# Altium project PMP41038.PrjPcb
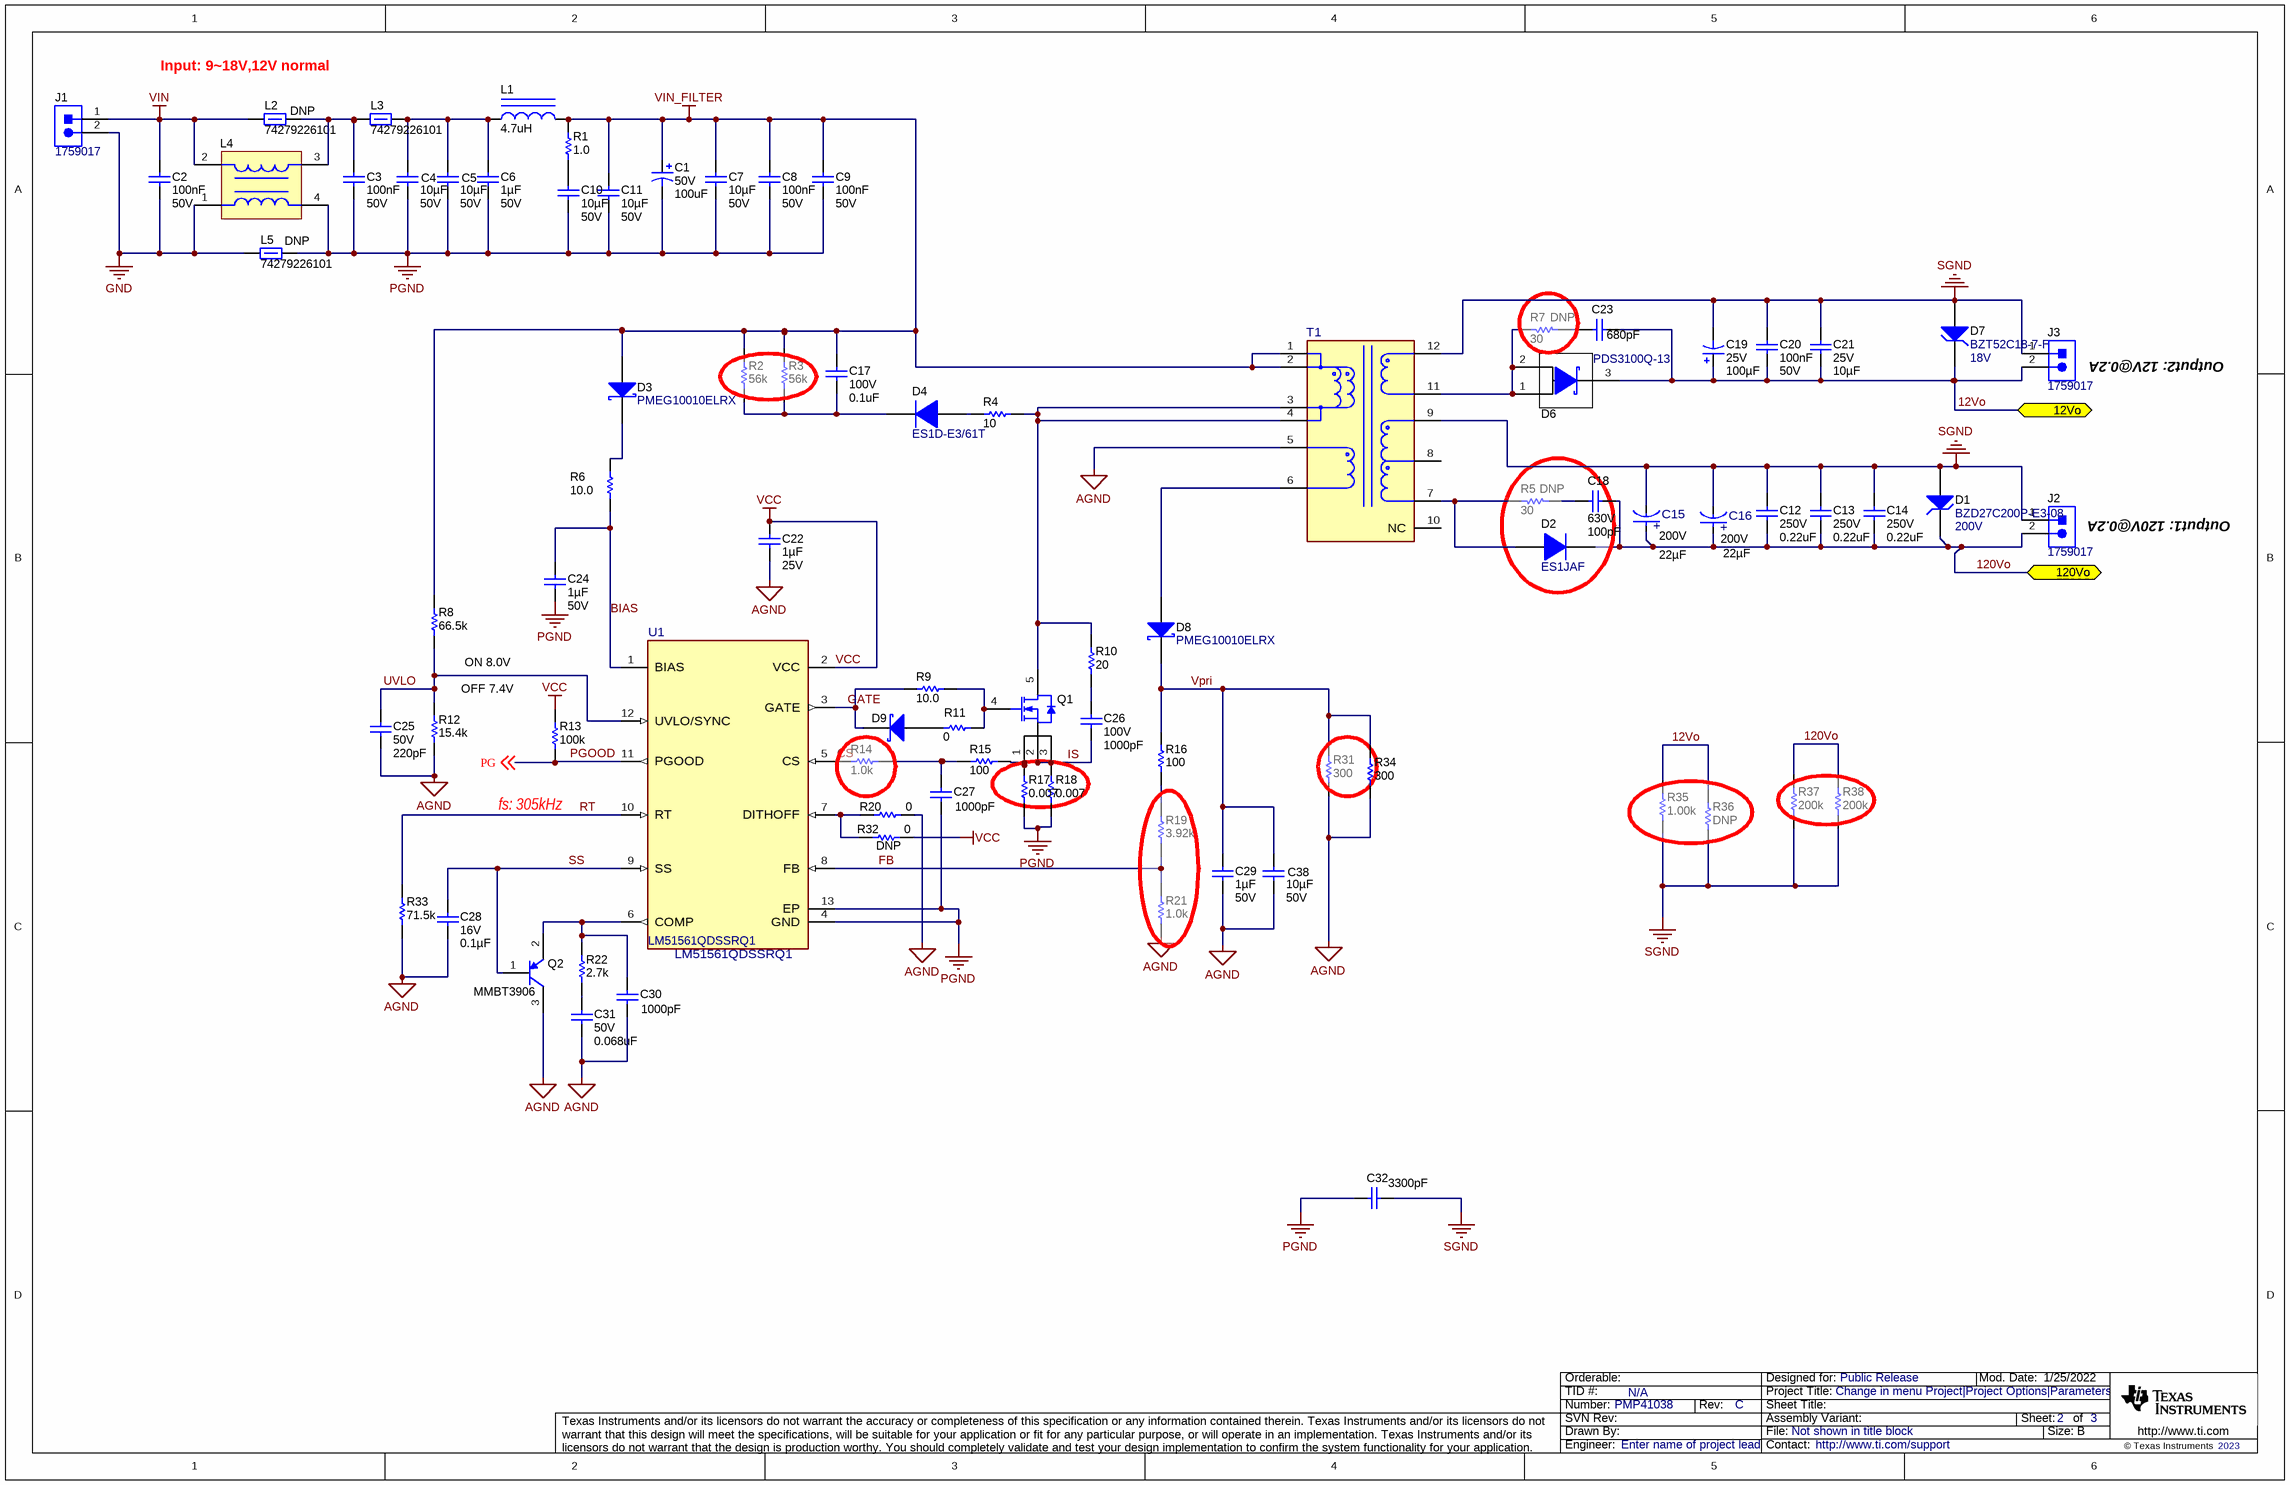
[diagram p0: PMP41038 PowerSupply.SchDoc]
CopyrightYear: 2023; PCB_Layout: Who did the Layout?; PCB_Rev: C; PRJ_Customer: Public Release; PRJ_Engineer: Enter name of project lead; PRJ_Number: PMP41038; PRJ_Title: Change in menu Project|Project Options|Parameters; SCH_Rev: C; TechSupport: http://www.ti.com/support; TID: N/A
3 sheets, 127 parts. Net scope: flat (ports and power ports of the same name join across sheets).
Board file: PMP41038.PcbDoc
Sheets:
  PMP41038 PowerSupply.SchDoc
  PMP41038_Hardware.SchDoc
  PMP41038 Driver.SchDoc

## Sheet PMP41038 PowerSupply.SchDoc
size 431 x 279 mm; Date: Not shown in title block; ApprovedBy: Not shown in title block; CheckedBy: Not shown in title block; Author: Not shown in title block; CompanyName: Not shown in title block; Engineer: Not shown in title block; Organization: Not shown in title block; Address1: Not shown in title block; Address2: Not shown in title block; Address3: Not shown in title block; Address4: Not shown in title block; DocumentNumber: 2; Revision: Use project parameter SCH_Rev; SheetNumber: 2; SheetTotal: 3; PageSetup: Record=PageOptions¦CenterHorizontal=True¦CenterVertical=True¦PrintScale=1.00¦XCorrection=1.00¦YCorrection=1.00¦PrintKind=0¦BorderSize=5000000¦LeftOffset=0¦BottomOffset=0¦Orientation=2¦PaperLength=1000¦PaperWidth=1000¦Scale=100¦PaperSource=15¦PrintQuality=600¦MediaType=1¦DitherType=10¦PaperKind=Letter¦PrintScaleMode=1

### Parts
C1  VDC_V: 50V  ValueDisplayed: 100uF  [SM_RADIAL_10BMM]  (hidden comment: EEHZA1H101P)
C2  Cap_F: 100nF  VDC_V: 50V  [0603]  (hidden comment: CGA3E2X7R1H104K080AA)
C3  Cap_F: 100nF  VDC_V: 50V  [0603]  (hidden comment: CGA3E2X7R1H104K080AA)
C4  ValueDisplayed: 10µF  VDC_V: 50V  [1206_190]  (hidden comment: CGA5L1X7R1H106K160AC)
C5  ValueDisplayed: 10µF  VDC_V: 50V  [1206_190]  (hidden comment: CGA5L1X7R1H106K160AC)
C6  Cap_F: 1µF  VDC_V: 50V  [0805_HV1]  (hidden comment: CGA4J3X7R1H105K125AB)
C7  ValueDisplayed: 10µF  VDC_V: 50V  [1206_190]  (hidden comment: CGA5L1X7R1H106K160AC)
C8  Cap_F: 100nF  VDC_V: 50V  [0603]  (hidden comment: CGA3E2X7R1H104K080AA)
C9  Cap_F: 100nF  VDC_V: 50V  [0603]  (hidden comment: CGA3E2X7R1H104K080AA)
C10  ValueDisplayed: 10µF  VDC_V: 50V  [1206_190]  (hidden comment: CGA5L1X7R1H106K160AC)
C11  ValueDisplayed: 10µF  VDC_V: 50V  [1206_190]  (hidden comment: CGA5L1X7R1H106K160AC)
C12  VDC_V: 250V  ValueDisplayed: 0.22uF  [1210_220]  (hidden comment: GRM32DR72E224KW01L)
C13  VDC_V: 250V  ValueDisplayed: 0.22uF  [1210_220]  (hidden comment: GRM32DR72E224KW01L)
C14  VDC_V: 250V  ValueDisplayed: 0.22uF  [1210_220]  (hidden comment: GRM32DR72E224KW01L)
C15  value 22µF  VDC_V: 200V  [FP-UVK2D220MPD_RADIAL-MFG]  (hidden comment: UVK2D220MPD)
C16  value 22µF  VDC_V: 200V  [FP-UVK2D220MPD_RADIAL-MFG]  (hidden comment: UVK2D220MPD)
C17  VDC_V: 100V  ValueDisplayed: 0.1uF  [1206_180]  (hidden comment: CGA5L2X7R2A104K160AA)
C18  VDC_V: 630V  ValueDisplayed: 100pF  [1206]  (hidden comment: GRM31A5C2J101JW01D)
C19  VDC_V: 25V  ValueDisplayed: 100µF  [Panasonic_D8]  (hidden comment: EEH-ZA1E101XP)
C20  Cap_F: 100nF  VDC_V: 50V  [0603]  (hidden comment: CGA3E2X7R1H104K080AA)
C21  VDC_V: 25V  ValueDisplayed: 10µF  [1206_190]  (hidden comment: CGA5L1X7R1E106K160AE)
C22  Cap_F: 1µF  VDC_V: 25V  [0603]  (hidden comment: GCM188R71E105KA64D)
C23  ValueDisplayed: 680pF  [0603]  (hidden comment: GRM1885C2A681JA01D)
C24  Cap_F: 1µF  VDC_V: 50V  [0805_HV]  (hidden comment: CGA4J3X7R1H105K125AB)
C25  VDC_V: 50V  ValueDisplayed: 220pF  [0402]  (hidden comment: CGA2B2X7R1H221K050BA)
C26  VDC_V: 100V  ValueDisplayed: 1000pF  [0603]  (hidden comment: GCM1885C2A102JA16D)
C27  ValueDisplayed: 1000pF  [0402]  (hidden comment: GCM155R71H102KA37D)
C28  VDC_V: 16V  ValueDisplayed: 0.1µF  [0402]  (hidden comment: GCM155R71C104JA55D)
C29  Cap_F: 1µF  VDC_V: 50V  [0805_HV1]  (hidden comment: CGA4J3X7R1H105K125AB)
C30  ValueDisplayed: 1000pF  [0402]  (hidden comment: GCM155R71H102KA37D)
C31  VDC_V: 50V  ValueDisplayed: 0.068uF  [0402]  (hidden comment: CGA2B3X7R1H683K050BB)
C32  ValueDisplayed: 3300pF  [CK45-RR_700x500x1100]  (hidden comment: CS95ZU2GA332MAGKA)
C38  ValueDisplayed: 10µF  VDC_V: 50V  [1206_190]  (hidden comment: CGA5L1X7R1H106K160AC)
D1  BZD27C200P-E3-08  value 200V  [DO-219AB]
D2  ES1JAF  [SMAF]
D3  PMEG10010ELRX  [SOD-123W]
D4  ES1D-E3/61T  [SMA]
D6  PDS3100Q-13  [POWERDI5]
D7  BZT52C18-7-F  value 18V  [SOD-123]
D8  PMEG10010ELRX  [SOD-123W]
D9  BAT54WSQ-7-F  [SOD-323]  (value not drawn)
J1  1759017  [Phoenix_1759017]
J2  1759017  [Phoenix_1759017]
J3  1759017  [Phoenix_1759017]
L1  ValueDisplayed: 4.7uH  [XAL5030]  (hidden comment: XAL5030-472MEB)
L2  74279226101  ValueDisplayed: DNP  [1812_170_HighSpeed]
L3  74279226101  [1812_170_HighSpeed]
L4  ACM1211-701-2PL-TL01  [TDK_ACM1211]  (value not drawn)
L5  74279226101  ValueDisplayed: DNP  [1812_170_HighSpeed]
Q1  NVMFS5C670NLWFAFT1G  [SO-8FL]  (value not drawn)
Q2  MMBT3906  [SOT-23]
R1  ValueDisplayed: 1.0  [0805_HV]  (hidden comment: RC0805JR-071RL)
R2  ValueDisplayed: 56k  [1206]  (hidden comment: CRCW120656K0JNEA)
R3  ValueDisplayed: 56k  [1206]  (hidden comment: CRCW120656K0JNEA)
R4  ValueDisplayed: 10  [1206]  (hidden comment: CRCW120610R0JNEA)
R5  value DNP  ValueDisplayed: 30  [1206]  (hidden comment: CRCW120630R0JNEA)
R6  ValueDisplayed: 10.0  [0603]  (hidden comment: CRCW060310R0FKEA)
R7  value DNP  ValueDisplayed: 30  [1206]  (hidden comment: CRCW120630R0JNEA)
R8  ValueDisplayed: 66.5k  [0402]  (hidden comment: CRCW040266K5FKED)
R9  ValueDisplayed: 10.0  [0603]  (hidden comment: CRCW060310R0FKEA)
R10  ValueDisplayed: 20  [1206]  (hidden comment: CRCW120620R0JNEA)
R11  ValueDisplayed: 0  [0603]  (hidden comment: CRCW06030000Z0EA)
R12  ValueDisplayed: 15.4k  [0402]  (hidden comment: CRCW040215K4FKED)
R13  ValueDisplayed: 100k  [0402]  (hidden comment: CRCW0402100KJNED)
R14  ValueDisplayed: 1.0k  [0402]  (hidden comment: ERJ-2GEJ102X)
R15  ValueDisplayed: 100  [0402]  (hidden comment: CRCW0402100RFKED)
R16  ValueDisplayed: 100  [0402]  (hidden comment: CRCW0402100RFKED)
R17  ValueDisplayed: 0.007  [PE1206]  (hidden comment: PE1206FRF470R007L)
R18  ValueDisplayed: 0.007  [PE1206]  (hidden comment: PE1206FRF470R007L)
R19  ValueDisplayed: 3.92k  [0402]  (hidden comment: CRCW04023K92FKED)
R20  ValueDisplayed: 0  [0402]  (hidden comment: CRCW04020000Z0ED)
R21  ValueDisplayed: 1.0k  [0402]  (hidden comment: ERJ-2GEJ102X)
R22  ValueDisplayed: 2.7k  [0402]  (hidden comment: CRCW04022K70JNED)
R31  ValueDisplayed: 300  [1206]  (hidden comment: RC1206FR-07300RL)
R32  value DNP  ValueDisplayed: 0  [0402]  (hidden comment: CRCW04020000Z0ED)
R33  ValueDisplayed: 71.5k  [0402]  (hidden comment: CRCW040271K5FKED)
R34  ValueDisplayed: 300  [1206]  (hidden comment: RC1206FR-07300RL)
R35  ValueDisplayed: 1.00k  [1206]  (hidden comment: RP73D2B1K0BTG)
R36  ValueDisplayed: DNP  [1206]  (hidden comment: RP73D2B1K0BTG)
R37  ValueDisplayed: 200k  [1206]  (hidden comment: CRCW1206200KFKEA)
R38  ValueDisplayed: 200k  [1206]  (hidden comment: CRCW1206200KFKEA)
T1  ZB1399-BL  [FP-ZB1399-BL_SMT_TRANSFORMER_30MM00_21MM13-MFG]  (value not drawn)
U1  LM51561QDSSRQ1  [DSS0012C-MFG]

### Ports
12Vo (bidir), 120Vo (bidir)

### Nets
AGND: C22.2 C25.2 C28.2 C29.2 C30.2 C31.2 C38.2 Q2.3(C) R12.1 R20.2 R21.1 R31.1 R33.1 R34.1 T1.5
GND: C2.2 J1.2 L4.1 L5.1
PGND: C1.2(-) C3.2 C4.2 C5.2 C6.2 C7.2 C8.2 C9.2 C10.2 C11.2 C24.2 C27.2 C32.2 L4.4 L5.2 R17.1 R18.1 U1.4(GND) U1.13(EP)
SGND: C12.1 C13.1 C14.1 C15.1(CATHODE) C16.1(CATHODE) C19.2(-) C20.1 C21.2 C32.1 D1.2(A) D7.2(A) J2.1 J3.1 R35.1 R36.1 R37.1 R38.1 T1.9 T1.12
VCC: C22.1 R13.2 R32.2 U1.2(VCC)
VIN: C2.1 J1.1 L2.1 L4.2
VIN_FILTER: C1.1(+) C7.1 C8.1 C9.1 C11.1 C17.1 D3.2(A) L1.2 R1.2 R2.2 R3.2 R8.2 T1.1 T1.2
12Vo: C19.1(+) C20.2 C21.1 C23.1 D6.3(K) D7.1(K) J3.2 R35.2 R36.2 ; port 12Vo
120Vo: C12.2 C13.2 C14.2 C15.2(ANODE) C16.2(ANODE) C18.1 D1.1(K) D2.1(K) J2.2 R37.2 R38.2 ; port 120Vo
BIAS: C24.1 R6.1 U1.1(BIAS)
CS: R14.2 U1.5(CS)
FB: R19.1 R21.2 U1.8(FB)
GATE: D9.1(K) R9.1 U1.3(GATE)
IS: C26.2 Q1.1(S) Q1.2(S) Q1.3(S) R15.2 R17.2 R18.2
PGOOD: R13.1 U1.11(PGOOD) ; off-sheet PG  [also labelled PG]
RT: R33.2 U1.10(RT)
SS: C28.1 Q2.1(B) U1.9(SS)
UVLO: C25.1 R8.1 R12.2 U1.12(UVLO/SYNC)
Vpri: C29.1 C38.1 D8.1(K) R16.2 R31.2 R34.2
NetC3_1: C3.1 L2.2 L3.1 L4.3
NetC4_1: C4.1 C5.1 C6.1 L1.1 L3.2
NetC10_1: C10.1 R1.1
NetC17_2: C17.2 D4.1(K) R2.1 R3.1
NetC18_2: C18.2 R5.2
NetC23_2: C23.2 R7.2
NetC26_1: C26.1 R10.1
NetC27_1: C27.1 R14.1 R15.1
NetC30_1: C30.1 Q2.2(E) R22.2 U1.6(COMP)
NetC31_1: C31.1 R22.1
NetD2_2: D2.2(A) R5.1 T1.7
NetD3_1: D3.1(K) R6.2
NetD4_2: D4.2(A) R4.1
NetD6_1: D6.1(A) D6.2(A) R7.1 T1.11
NetD8_2: D8.2(A) T1.6
NetD9_2: D9.2(A) R11.2
NetQ1_4: Q1.4(G) R9.2 R11.1
NetQ1_5: Q1.5(D) R4.2 R10.2 T1.3 T1.4
NetR16_1: R16.1 R19.2
NetR20_1: R20.1 R32.1 U1.7(DITHOFF)

Not connected (* = marked no-connect by the designer): T1 8 10(NC)

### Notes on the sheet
- Input: 9
  8V,12V normal
- (near J3) Output2: 12V@0.2A
- (near J2) Output1: 120V@0.2A
- ON 8.0V
- OFF 7.4V
- (near R13) fs: 305kHz

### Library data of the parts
C1 = CMP-0012576-3: CAP, Polymer Hybrid, 100 uF, 50 V, +/- 20%, 28 ohm, 10x10 SMD; Manufacturer: Panasonic; TaMin_C: -55°C; ESR_ohm: 28; Polarized: Y; SizeAreaWB_mm2: 159.9; Value1: 28 ohm; Value: 100uF; TaMax_C: 105°C; SizeZ_mm: 10.2; SizeX_mm: 11; SizeY_mm: 10.3; SizeArea_mm2: 113.3; CompType: Capacitor; Cap_F: 100µF; IRMS_A: 2A; AEC Category: Q200
C2 C3 C8 C9 C20 = CMP-0007078-2: CAP, CERM, 0.1 uF, 50 V, +/- 10%, X7R, AEC-Q200 Grade 1, 0603; Manufacturer: TDK; TaMin_C: -55°C; Polarized: N; SizeAreaWB_mm2: 4.68; Value1: 0.0296 ohm; U/M: EA; Value: 0.1uF; TaMax_C: 125°C; SizeZ_mm: 1; SizeX_mm: 1.6; SizeY_mm: 0.8; SizeArea_mm2: 1.28; AEC Qualified: Y; AEC Category: Q200; ESR_ohm: 0.0296; IRMS_A: 971.99mA
C4 C5 C7 C10 C11 C38 = CMP-0085950-1: CAP, CERM, 10 µF, 50 V,+/- 10%, X7R, AEC-Q200 Grade 1, 1206; Manufacturer: TDK; SizeZ_mm: 1.9; Value: 10uF; Cap_Case: 1206; AEC Grade: 1; TaMin_C: -55°C; U/M: EA; SizeArea_mm2: 5.12; TaMax_C: 125°C; AEC Qualified: Y; AEC Category: Q200; SizeX_mm: 3.2; SizeY_mm: 1.6; Polarized: N; SizeAreaWB_mm2: 10.92
C6 C29 = CMP-0007976-1: CAP, CERM, 1 uF, 50 V, +/- 10%, X7R, AEC-Q200 Grade 1, 0805; Manufacturer: TDK; TaMin_C: -55°C; ESR_ohm: 8.782m; Polarized: N; SizeAreaWB_mm2: 6.75; Value1: 0.008782 ohm; U/M: EA; Value: 1uF; TaMax_C: 125°C; SizeZ_mm: 1.45; SizeX_mm: 2; SizeY_mm: 1.25; Cap_Case: 0805; SizeArea_mm2: 2.5; AEC Qualified: Y; IRMS_A: 2.20488A; AEC Grade: 1; AEC Category: Q200
C12-C14 = CMP-0009193-2: CAP, CERM, 0.22 uF, 250 V, +/- 10%, X7R, 1210; Manufacturer: MuRata; TaMin_C: -55°C; Polarized: N; SizeAreaWB_mm2: 14.7; Value1: Unknown; U/M: EA; Value: 0.22uF; TaMax_C: 125°C; SizeZ_mm: 2.2; SizeX_mm: 3.2; SizeY_mm: 2.5; Cap_Case: 1210; SizeArea_mm2: 8; Cap_F: 220nF; AEC Category: Q200
C15 C16 = CMP-0096325-1: 22 µF 200 V Aluminum Electrolytic Capacitors Radial, Can 2000 Hrs @ 85°C; Manufacturer: Nichicon; IRMS_A: 150mA; SizeZ_mm: 17.5mm; ValueDisplayed: 22uF; Leakage Current: 276uA; AEC Qualified: No; Tolerance_%: 20%; Life: 2000Hours
C17 = CMP-0008778-1: CAP, CERM, 0.1 uF, 100 V, +/- 10%, X7R, AEC-Q200 Grade 1, 1206; Manufacturer: TDK; TaMin_C: -55°C; ESR_ohm: 0.030343; Polarized: N; SizeAreaWB_mm2: 10.92; Value1: 0.030343 ohm; U/M: EA; Value: 0.1uF; TaMax_C: 125°C; SizeZ_mm: 1.8; SizeX_mm: 3.2; SizeY_mm: 1.6; SizeArea_mm2: 5.12; AEC Qualified: Y; Cap_F: 100nF; IRMS_A: 1.33802A; AEC Grade: 1; AEC Category: Q200
C18 = CMP-0008884-2: CAP, CERM, 100 pF, 630 V, +/- 5%, C0G/NP0, 1206; Manufacturer: MuRata; TaMin_C: -55°C; Polarized: N; SizeAreaWB_mm2: 10.92; Value1: Unknown; U/M: EA; Value: 100pF; TaMax_C: 125°C; SizeZ_mm: 1.35; SizeX_mm: 3.2; SizeY_mm: 1.6; SizeArea_mm2: 5.12; AEC Category: Q200
C19 = CMP-0860234-1: CAP, Aluminum Polymer, 100 µF, 25 V,+/- 20%, 0.03 ohm, AEC-Q200 Grade 2, D6.3xL7.7mm SMD; Manufacturer: Panasonic; Cap_Case: 6.3x7.7mm; TaMax_C: 105°C; AEC Qualified: Y; SizeY_mm: 6.6; TaMin_C: -55°C; Value: 100uF; SizeAreaWB_mm2: 73.96; CompType: Capacitor; SizeArea_mm2: 43.56; IRMS_A: 2A; AEC Grade: 2; AEC Category: Q200; SizeZ_mm: 8; ESR_ohm: 0.03
C21 = CMP-0085253-1: CAP, CERM, 10 µF, 25 V,+/- 10%, X7R, AEC-Q200 Grade 1, 1206; Manufacturer: TDK; SizeAreaWB_mm2: 10.92; SizeArea_mm2: 5.12; AEC Qualified: Y; AEC Category: Q200; Value: 10uF; TaMax_C: 125°C; SizeZ_mm: 1.9; AEC Grade: 1; Polarized: N; TaMin_C: -55°C; SizeY_mm: 1.6; U/M: EA; SizeX_mm: 3.2; Cap_Case: 1206
C22 = CMP-0007139-1: CAP, CERM, 1 uF, 25 V, +/- 10%, X7R, AEC-Q200 Grade 1, 0603; Manufacturer: MuRata; TaMin_C: -55°C; Polarized: N; SizeAreaWB_mm2: 4.68; Value1: Unknown; U/M: EA; Value: 1uF; TaMax_C: 125°C; SizeZ_mm: 1; SizeX_mm: 1.6; SizeY_mm: 0.8; SizeArea_mm2: 1.28; AEC Qualified: Y; AEC Category: Q200
C23 = CMP-0007281-4: CAP, CERM, 680 pF, 100 V, +/- 5%, C0G/NP0, 0603; Manufacturer: MuRata; Value1: Unknown; SizeArea_mm2: 1.28; SizeAreaWB_mm2: 4.68; Value: 680pF; U/M: EA; Value2: 100V; TaMax_C: 125°C; TaMin_C: -55°C; SizeY_mm: 0.8; AEC Category: Q200; SizeZ_mm: 1; Polarized: N; SizeX_mm: 1.6
C24 = CMP-0007976-2: CAP, CERM, 1 uF, 50 V, +/- 10%, X7R, AEC-Q200 Grade 1, 0805; Manufacturer: TDK; TaMin_C: -55°C; ESR_ohm: 8.782m; Polarized: N; SizeAreaWB_mm2: 6.75; Value1: 0.008782 ohm; U/M: EA; Value: 1uF; TaMax_C: 125°C; SizeZ_mm: 1.45; SizeX_mm: 2; SizeY_mm: 1.25; Cap_Case: 0805; SizeArea_mm2: 2.5; AEC Qualified: Y; IRMS_A: 2.20488A; AEC Grade: 1; AEC Category: Q200
C25 = CMP-0006316-1: CAP, CERM, 220 pF, 50 V, +/- 10%, X7R, AEC-Q200 Grade 1, 0402; Manufacturer: TDK; TaMin_C: -55°C; ESR_ohm: 9.829; Polarized: N; SizeAreaWB_mm2: 3; Value1: 9.829 ohm; U/M: EA; Value: 220pF; TaMax_C: 125°C; SizeZ_mm: 0.6; SizeX_mm: 1; SizeY_mm: 0.5; AEC Qualified: Y; IRMS_A: 201.345mA; AEC Category: Q200
C26 = CMP-0007131-4: CAP, CERM, 1000 pF, 100 V, +/- 5%, C0G/NP0, AEC-Q200 Grade 1, 0603; Manufacturer: MuRata; TaMin_C: -55°C; Polarized: N; SizeAreaWB_mm2: 4.68; Value1: Unknown; U/M: EA; Value: 1000pF; TaMax_C: 125°C; SizeZ_mm: 1; SizeX_mm: 1.6; SizeY_mm: 0.8; SizeArea_mm2: 1.28; AEC Qualified: Y; Cap_F: 1nF; AEC Category: Q200
C27 C30 = CMP-0006354-2: CAP, CERM, 1000 pF, 50 V, +/- 10%, X7R, AEC-Q200 Grade 1, 0402; Manufacturer: MuRata; TaMin_C: -55°C; Polarized: N; SizeAreaWB_mm2: 3; Value1: Unknown; U/M: EA; Value: 1000pF; TaMax_C: 125°C; SizeZ_mm: 0.6; SizeX_mm: 1; SizeY_mm: 0.5; Value2: 50V; AEC Qualified: Y; Cap_F: 1nF; AEC Category: Q200
C28 = CMP-0080702-1: CAP, CERM, 0.1 µF, 16 V,+/- 5%, X7R, AEC-Q200 Grade 1, 0402; Manufacturer: MuRata; Cap_F: 100nF; SizeAreaWB_mm2: 3; SizeArea_mm2: 0.5; AEC Qualified: Y; AEC Category: Q200; Value: 0.1uF; TaMax_C: 125°C; SizeZ_mm: 0.6; AEC Grade: 1; Polarized: N; TaMin_C: -55°C; U/M: EA
C31 = CMP-0006331-2: CAP, CERM, 0.068 uF, 50 V, +/- 10%, X7R, AEC-Q200 Grade 1, 0402; Manufacturer: TDK; TaMin_C: -55°C; ESR_ohm: 0.05606; Polarized: N; SizeAreaWB_mm2: 3; Value1: 0.05606 ohm; U/M: EA; TaMax_C: 125°C; SizeZ_mm: 0.6; SizeX_mm: 1; SizeY_mm: 0.5; AEC Qualified: Y; Cap_F: 68nF; IRMS_A: 684.724mA; AEC Category: Q200
C32 = CMP-0077187-1: CAP, CERM, 3300 pF, 2000 V,+/- 10%, R, 7x5mm; Manufacturer: TDK; SizeAreaWB_mm2: 63.0; SizeArea_mm2: 35.0; AEC Qualified: N; AEC Category: Q200; Value: 3300pF; TaMax_C: 125°C; SizeZ_mm: 11.0; TaMin_C: -25°C; SizeY_mm: 5.0; Value2: 2000V; U/M: EA; SizeX_mm: 7.0; Cap_Case: 7x5x11mm
D1 = CMP-0065107-4: Diode, Zener, 200 V, 800 mW, AEC-Q101, DO-219AB; Manufacturer: Vishay-Semiconductor; Power_W: 800mW; SizeY_mm: 1.8; RJA_CperW: 180; Value1: 0.8W; SizeAreaWB_mm2: 13.16; AEC Category: Q101; AEC Qualified: Y; SizeX_mm: 3.7; SizeZ_mm: 1.08; SizeArea_mm2: 6.66
D2 = CMP-0029162-1: Diode, Ultrafast, 600 V, 1 A, AEC-Q101, SMAF; Manufacturer: Fairchild Semiconductor; Io_A: 1A; Green_Lifecycle: Not Set; SizeAreaWB_mm2: 19.95; Vr_V: 600V; Green_REACh: Incomplete; TJmax_C: 150°C; U/M: EA; Value: 600V; SizeZ_mm: 1; SizeX_mm: 4.7; SizeY_mm: 2.5; Vf_V: 1.7V; SizeArea_mm2: 11.75; AEC Qualified: Y; AEC Category: Q101
D3 D8 = CMP-0028782-1: Diode, Schottky, 100 V, 1 A, AEC-Q101, SOD-123W; Manufacturer: Nexperia; Io_A: 1A; Green_Lifecycle: Not Set; SizeAreaWB_mm2: 12.15; Vr_V: 100V; Green_REACh: Incomplete; TJmax_C: 175°C; U/M: EA; Value: 100V; SizeZ_mm: 1; SizeX_mm: 3.5; SizeY_mm: 1.7; Vf_V: 770mV; Value2: 0.77V; SizeArea_mm2: 5.95; AEC Qualified: Y; AEC Category: Q101
D4 = CMP-0082147-1: Diode, Ultrafast, 200 V, 1 A, AEC-Q101, SMA; Manufacturer: Vishay-Semiconductor; SizeAreaWB_mm2: 37.3428; Vr_V: 200V; SizeArea_mm2: 16.3228; AEC Qualified: Y; TJmax_C: 150°C; AEC Category: Q101; Value: 200V; SizeZ_mm: 2.87; Io_A: 1A; Vf_V: 920mV; SizeY_mm: 2.92; Value2: 0.92V; SizeX_mm: 5.59
D6 = CMP-0028754-1: Diode, Schottky, 100 V, 3 A, AEC-Q101, PowerDI5; Manufacturer: Diodes Inc.; Value: 100V; Value1: 3A; SizeZ_mm: 1.05; Green_REACh: Passed; Value2: 0.76V; SizeArea_mm2: 24.96; AEC Qualified: Y; SizeY_mm: 3.9; TJmax_C: 150°C; SizeAreaWB_mm2: 49.56; SizeX_mm: 6.4; Vf_V: 760mV; AEC Category: Q101; Green_Lifecycle: Active; U/M: EA
D7 = CMP-0084402-1: Diode, Zener, 18 V, 500 mW, AEC-Q101, SOD-123; Manufacturer: Diodes Inc.; AEC Category: Q101; Value1: 0.5W; SizeArea_mm2: 6.545; AEC Qualified: Y; Green_Lifecycle: Active; Power_W: 500mW; SizeZ_mm: 1.35; Green_REACh: Incomplete; SizeY_mm: 1.7; SizeAreaWB_mm2: 13.095; SizeX_mm: 3.85; RJA_CperW: 338
D9 = CMP-0081199-2: Diode, Schottky, 30 V, 0.1 A, AEC-Q101, SOD-323; Manufacturer: Diodes Inc.; Value1: 0.1A; SizeArea_mm2: 3.645; Value: 30V; Vf_V: 1V; Io_A: 100mA; TJmax_C: 150°C; SizeY_mm: 1.35; SizeX_mm: 2.7; AEC Qualified: Y; SizeAreaWB_mm2: 8.695; SizeZ_mm: 1; AEC Category: Q101
J1-J3 = CMP-0055551-1: Header (Shrouded), 5.08mm, 2x1, Tin, R/A, TH; Manufacturer: Phoenix Contact; Cert_VDE: Y; CNHeader: FALSE; Current_A: 12A; Green_Lifecycle: Not Set; Gender: Male; Green_REACh: Incomplete; Voltage_V: 400V; Row_Count: 1; Pitch_mm: 5.08
L1 = CMP-0061004-2: Inductor, Shielded, Composite, 4.7 µH, 5.9 A, 0.04 ohm, AEC-Q200 Grade 1, SMD; Manufacturer: Coilcraft; Isat: 6.7A @ 30% inductance drop; Irms: 5.9A @ 40C rise; Green_Lifecycle: Not Set; SizeAreaWB_mm2: 54.4544; DCR_ohm: 0.04; Green_REACh: Incomplete; Value: 4.7uH; Imax_A: 5.9A; SizeZ_mm: 3.1; SizeX_mm: 5.28; SizeY_mm: 5.48; SizeArea_mm2: 28.9344; Ind_H: 4.7µH; AEC Qualified: 1; AEC Category: Q200; AEC Grade: Y
L2 L3 L5 = CMP-0003152-1: Ferrite Bead, 100 ohm @ 100 MHz, 8 A, 1812; Manufacturer: Wurth Elektronik; Ztyp@1GHz_Ohm: 156.481; ZTyp@100MHz_Ohm: 100; SizeAreaWB_mm2: 23.1; DCR_ohm: 6m; Value1: 0.006 ohm; Value: 100 ohm; Imax_A: 8A; SizeZ_mm: 1.7; SizeX_mm: 4.5; SizeY_mm: 3.2; SizeArea_mm2: 14.4
L4 = CMP-0013118-2: Coupled inductor, 8 A, 0.006 ohm, SMD; Manufacturer: TDK; DCR_ohm: 6m
Q1 = CMP-0750168-1: MOSFET, N-CH, 60 V, 17 A, AEC-Q101, SO-8FL; Alternate Manufacturer: None; Manufacturer: ON Semiconductor; SizeAreaWB_mm2: 58.2725; Value1: 0.0088 ohm; ChType: N; QgTyp_nC: 20; SizeArea_mm2: 31.6725; Vgs_V: 20V; SizeX_mm: 6.15; SizeZ_mm: 1.1; SizeY_mm: 5.15; Value2: 20 nC; IdsMax_A: 17A; AEC Qualified: Y; ChMode: Enhancement; AEC Category: Q101; Rdson45_ohm: 8.8m; VdsMax_V: 60V; Value: 60V
Q2 = CMP-0000325-2: Transistor, PNP, 40 V, 0.2 A, SOT-23; Manufacturer: Fairchild Semiconductor; TaMax_C: 150°C; Value2: 300; Value1: 0.2 A; Vcesat1_V: 2.5dV; SizeX_mm: 2.5; SizeY_mm: 3; TaMin_C: -55°C; IcRated_A: 2dA; CompType: BJT; SizeZ_mm: 1.1; Value: 40 V; SizeArea_mm2: 7.5; NPN: 0; Vceo_V: 40V; PNP: 1; AEC Category: Q101; SizeAreaWB_mm2: 14; U/M: EA
R1 = CMP-0020811-2: RES, 1.0, 5%, 0.125 W, 0805; Manufacturer: Yageo America; Power_W: 125mW; TempCo: 200 ppm/C; Value_Code: 1R00; U/M: EA; Value: 1.0; EIA_Code: E24; Res_ohm: 1; SizeX_mm: 2; SizeY_mm: 1.25; SizeZ_mm: 1.45; Value2: 0.125W; SizeArea_mm2: 2.5; VDC_V: 150V; AEC Category: Q200
R2 R3 = CMP-0018701-3: RES, 56 k, 5%, 0.25 W, AEC-Q200 Grade 0, 1206; Manufacturer: Vishay-Dale; Power_W: 250mW; TempCo: 200 ppm/C; Value_Code: 56k0; Value: 56k; EIA_Code: E24; SizeX_mm: 3.2; SizeY_mm: 1.6; SizeZ_mm: 1.35; Value2: 0.25W; SizeArea_mm2: 5.12; AEC Qualified: Y; VDC_V: 200V; AEC Category: Q200; AEC Grade: 0
R4 = CMP-0018578-3: RES, 10, 5%, 0.25 W, AEC-Q200 Grade 0, 1206; Manufacturer: Vishay-Dale; Power_W: 250mW; TempCo: 200 ppm/C; Value_Code: 10R0; Value: 10; EIA_Code: E24; SizeX_mm: 3.2; SizeY_mm: 1.6; SizeZ_mm: 1.35; Value2: 0.25W; SizeArea_mm2: 5.12; AEC Qualified: Y; VDC_V: 200V; AEC Category: Q200; AEC Grade: 0
R5 R7 = CMP-0018655-3: RES, 30, 5%, 0.25 W, AEC-Q200 Grade 0, 1206; Manufacturer: Vishay-Dale; Power_W: 250mW; TempCo: 200 ppm/C; Value_Code: 30R0; EIA_Code: E24; SizeX_mm: 3.2; SizeY_mm: 1.6; SizeZ_mm: 1.35; Value2: 0.25W; SizeArea_mm2: 5.12; AEC Qualified: Y; AEC Grade: 0; AEC Category: Q200; VDC_V: 200V
R6 R9 = CMP-0022003-4: RES, 10.0, 1%, 0.1 W, AEC-Q200 Grade 0, 0603; Manufacturer: Vishay-Dale; Power_W: 100mW; TempCo: 100 ppm/C; Value_Code: 10R0; Value: 10.0; EIA_Code: E96; Res_ohm: 10; SizeX_mm: 1.6; SizeY_mm: 0.8; SizeZ_mm: 1; Value2: 0.1W; SizeArea_mm2: 1.28; AEC Qualified: Y; VDC_V: 75V; AEC Category: Q200; AEC Grade: 0
R8 = CMP-0026502-2: RES, 66.5 k, 1%, 0.063 W, AEC-Q200 Grade 0, 0402; Manufacturer: Vishay-Dale; Power_W: 63mW; TempCo: 100 ppm/C; Value_Code: 66k5; Value: 66.5k; EIA_Code: E96; SizeX_mm: 1; SizeY_mm: 0.5; SizeZ_mm: 0.6; Value2: 0.063W; AEC Qualified: Y; VDC_V: 50V; AEC Category: Q200; AEC Grade: 0
R10 = CMP-0018627-3: RES, 20, 5%, 0.25 W, AEC-Q200 Grade 0, 1206; Manufacturer: Vishay-Dale; Power_W: 250mW; TempCo: 200 ppm/C; Value_Code: 20R0; Value: 20; EIA_Code: E24; SizeX_mm: 3.2; SizeY_mm: 1.6; SizeZ_mm: 1.35; Value2: 0.25W; SizeArea_mm2: 5.12; AEC Qualified: Y; VDC_V: 200V; AEC Category: Q200; AEC Grade: 0
R11 = CMP-0025697-4: RES, 0, 5%, 0.1 W, AEC-Q200 Grade 0, 0603; Manufacturer: Vishay-Dale; Power_W: 100mW; TempCo: 200 ppm/C; Value_Code: 0000; Value: 0; EIA_Code: E24; SizeX_mm: 1.6; SizeY_mm: 0.8; SizeZ_mm: 1; Value2: 0.1W; SizeArea_mm2: 1.28; AEC Qualified: Y; VDC_V: 75V; AEC Category: Q200
R12 = CMP-0026028-3: RES, 15.4 k, 1%, 0.063 W, AEC-Q200 Grade 0, 0402; Manufacturer: Vishay-Dale; Power_W: 63mW; TempCo: 100 ppm/C; Value_Code: 15k4; Value: 15.4k; EIA_Code: E96; SizeX_mm: 1; SizeY_mm: 0.5; SizeZ_mm: 0.6; Value2: 0.063W; AEC Qualified: Y; VDC_V: 50V; AEC Category: Q200; AEC Grade: 0
R13 = CMP-0026823-3: RES, 100 k, 5%, 0.063 W, AEC-Q200 Grade 0, 0402; Manufacturer: Vishay-Dale; Power_W: 63mW; TempCo: 200 ppm/C; Value: 100k; EIA_Code: E24; SizeX_mm: 1; SizeY_mm: 0.5; SizeZ_mm: 0.6; Value2: 0.063W; AEC Qualified: Y; VDC_V: 50V; AEC Category: Q200; AEC Grade: 0
R14 R21 = CMP-0078193-1: RES, 1.0 k, 5%, 0.1 W, AEC-Q200 Grade 0, 0402; Manufacturer: Panasonic; Value_Code: 1k00; SizeArea_mm2: 0.5; AEC Qualified: Y; AEC Category: Q200; Res_ohm: 1k; Value: 1.0k; SizeZ_mm: 0.6; Green_REACh: Passed; EIA_Code: E24; TempCo: 200 ppm/C; AEC Grade: 0; Power_W: 100mW; VDC_V: 50V; Value2: 0.1W; Green_Lifecycle: Active; U/M: EA; SizeX_mm: 1
R15 R16 = CMP-0025951-3: RES, 100, 1%, 0.063 W, AEC-Q200 Grade 0, 0402; Manufacturer: Vishay-Dale; Power_W: 63mW; TempCo: 100 ppm/C; Value_Code: 100R; Value: 100; EIA_Code: E96; SizeX_mm: 1; SizeY_mm: 0.5; SizeZ_mm: 0.6; Value2: 0.063W; AEC Qualified: Y; VDC_V: 50V; AEC Category: Q200; AEC Grade: 0
R17 R18 = CMP-0017834-1: RES, 0.007, 1%, 1 W, AEC-Q200 Grade 0, 1206; Manufacturer: Yageo America; Power_W: 1W; TempCo: 100 ppm/C; Value_Code: 7L000; U/M: EA; Value: 0.007; EIA_Code: E96; Res_ohm: 7m; SizeX_mm: 3.2; SizeY_mm: 1.6; SizeZ_mm: 0.89; SizeArea_mm2: 5.12; AEC Qualified: Y; AEC Grade: 0; AEC Category: Q200
R19 = CMP-0026340-1: RES, 3.92 k, 1%, 0.063 W, 0402; Manufacturer: Vishay-Dale; Power_W: 63mW; TempCo: 100 ppm/C; Value_Code: 3k92; U/M: EA; Value: 3.92k; EIA_Code: E96; SizeX_mm: 1; SizeY_mm: 0.5; SizeZ_mm: 0.6; Value2: 0.063W; VDC_V: 50V; AEC Category: Q200
R20 = CMP-0026822-3: RES, 0, 5%, 0.063 W, AEC-Q200 Grade 0, 0402; Manufacturer: Vishay-Dale; Power_W: 63mW; TempCo: 200 ppm/C; Value_Code: 0000; Value: 0; EIA_Code: E24; SizeX_mm: 1; SizeY_mm: 0.5; SizeZ_mm: 0.6; Value2: 0.063W; AEC Qualified: Y; VDC_V: 50V; AEC Category: Q200
R22 = CMP-0026892-5: RES, 2.7 k, 5%, 0.063 W, AEC-Q200 Grade 0, 0402; Manufacturer: Vishay-Dale; Power_W: 63mW; TempCo: 200 ppm/C; Value_Code: 2k70; Value: 2.7k; EIA_Code: E24; SizeX_mm: 1; SizeY_mm: 0.5; SizeZ_mm: 0.6; Value2: 0.063W; AEC Qualified: Y; VDC_V: 50V; AEC Category: Q200; AEC Grade: 0
R31 R34 = CMP-0018186-1: RES, 300, 1%, 0.25 W, 1206; Manufacturer: Yageo America; Power_W: 250mW; TempCo: 100 ppm/C; Value_Code: 300R; U/M: EA; Value: 300; SizeX_mm: 3.2; SizeY_mm: 1.6; SizeZ_mm: 1.35; Value2: 0.25W; SizeArea_mm2: 5.12; VDC_V: 200V; AEC Category: Q200
R32 = CMP-0026822-3: RES, 0, 5%, 0.063 W, AEC-Q200 Grade 0, 0402; Manufacturer: Vishay-Dale; Power_W: 63mW; TempCo: 200 ppm/C; Value_Code: 0000; EIA_Code: E24; SizeX_mm: 1; SizeY_mm: 0.5; SizeZ_mm: 0.6; Value2: 0.063W; AEC Qualified: Y; VDC_V: 50V; AEC Category: Q200
R33 = CMP-0026535-2: RES, 71.5 k, 1%, 0.063 W, AEC-Q200 Grade 0, 0402; Manufacturer: Vishay-Dale; Power_W: 63mW; TempCo: 100 ppm/C; Value_Code: 71k5; Value: 71.5k; EIA_Code: E96; SizeX_mm: 1; SizeY_mm: 0.5; SizeZ_mm: 0.6; Value2: 0.063W; AEC Qualified: Y; VDC_V: 50V; AEC Category: Q200; AEC Grade: 0
R35 = CMP-0018797-2: RES, 1.00 k, 0.1%, 0.25 W, 1206; Manufacturer: TE Connectivity; Power_W: 250mW; TempCo: 15 ppm/C; Value_Code: 1k00; U/M: EA; Value: 1.00k; EIA_Code: E192; Res_ohm: 1k; SizeX_mm: 3.2; SizeY_mm: 1.6; SizeZ_mm: 1.35; Value2: 0.25W; SizeArea_mm2: 5.12; AEC Qualified: N; VDC_V: 200V; AEC Category: Q200
R36 = CMP-0018797-2: RES, 1.00 k, 0.1%, 0.25 W, 1206; Manufacturer: TE Connectivity; Power_W: 250mW; TempCo: 15 ppm/C; Value_Code: 1k00; U/M: EA; Value: 1.00k; EIA_Code: E192; Res_ohm: 1K; SizeX_mm: 3.2; SizeY_mm: 1.6; SizeZ_mm: 1.35; Value2: 0.25W; SizeArea_mm2: 5.12; AEC Qualified: N; VDC_V: 200V; AEC Category: Q200
R37 R38 = CMP-0016775-3: RES, 200 k, 1%, 0.25 W, AEC-Q200 Grade 0, 1206; Manufacturer: Vishay-Dale; Power_W: 250mW; TempCo: 100 ppm/C; Value: 200k; EIA_Code: E96; SizeX_mm: 3.2; SizeY_mm: 1.6; SizeZ_mm: 1.35; Value2: 0.25W; SizeArea_mm2: 5.12; AEC Qualified: Y; VDC_V: 200V; AEC Category: Q200; AEC Grade: 0
T1 = CMP-0091232-2: EFD20 12PIN SMD FLYBACK TRANSFORMER; Manufacturer: Coilcraft; SizeZ_mm: 11.43mm; Ns1toNp: 1:0.2855:0.1425:0.095:0.333; AEC Qualified: No; Frequency_Fixed: 100kHz; Ind_H: 135µH; Voltage_Isolation_Vrms: 3000Vrms
U1 = CMP-0088384-2: 2.2-MHz Wide VIN 65-V Non-synchronous Boost/SEPIC/Flyback Controller with Dual Random Spread Spectrum; Manufacturer: Texas Instruments; Switching Frequency: 100-2200kHz; AEC Category: Q200; TaMax_C: +125°C; Min Supply Voltage: 1.5V; Max Supply Voltage: 60V; Max Duty Cycle: 96%; TaMin_C: -40°C; TJmax_C: +150°C; Output Type: Other; CompType: IC; AEC Grade: Grade 1; Standoff Height: 0mm; AEC Qualified: Yes; Switching Topology: Boost,Flyback,Other; Nominal Supply Current: 490uA; Number Of Outputs: 1; SizeZ_mm: 0.8mm

## Sheet PMP41038_Hardware.SchDoc
size 431 x 279 mm; Date: Not shown in title block; ApprovedBy: Not shown in title block; CheckedBy: Not shown in title block; Author: Not shown in title block; CompanyName: Not shown in title block; Engineer: Not shown in title block; Organization: Not shown in title block; Address1: Not shown in title block; Address2: Not shown in title block; Address3: Not shown in title block; Address4: Not shown in title block; DocumentNumber: 3; Revision: Use project parameter SCH_Rev; SheetNumber: 3; SheetTotal: 3; PageSetup: Record=PageOptions¦CenterHorizontal=True¦CenterVertical=True¦PrintScale=1.00¦XCorrection=1.00¦YCorrection=1.00¦PrintKind=0¦BorderSize=5000000¦LeftOffset=0¦BottomOffset=0¦Orientation=2¦PaperLength=1000¦PaperWidth=1000¦Scale=100¦PaperSource=15¦PrintQuality=600¦MediaType=1¦DitherType=10¦PaperKind=Letter¦PrintScaleMode=1
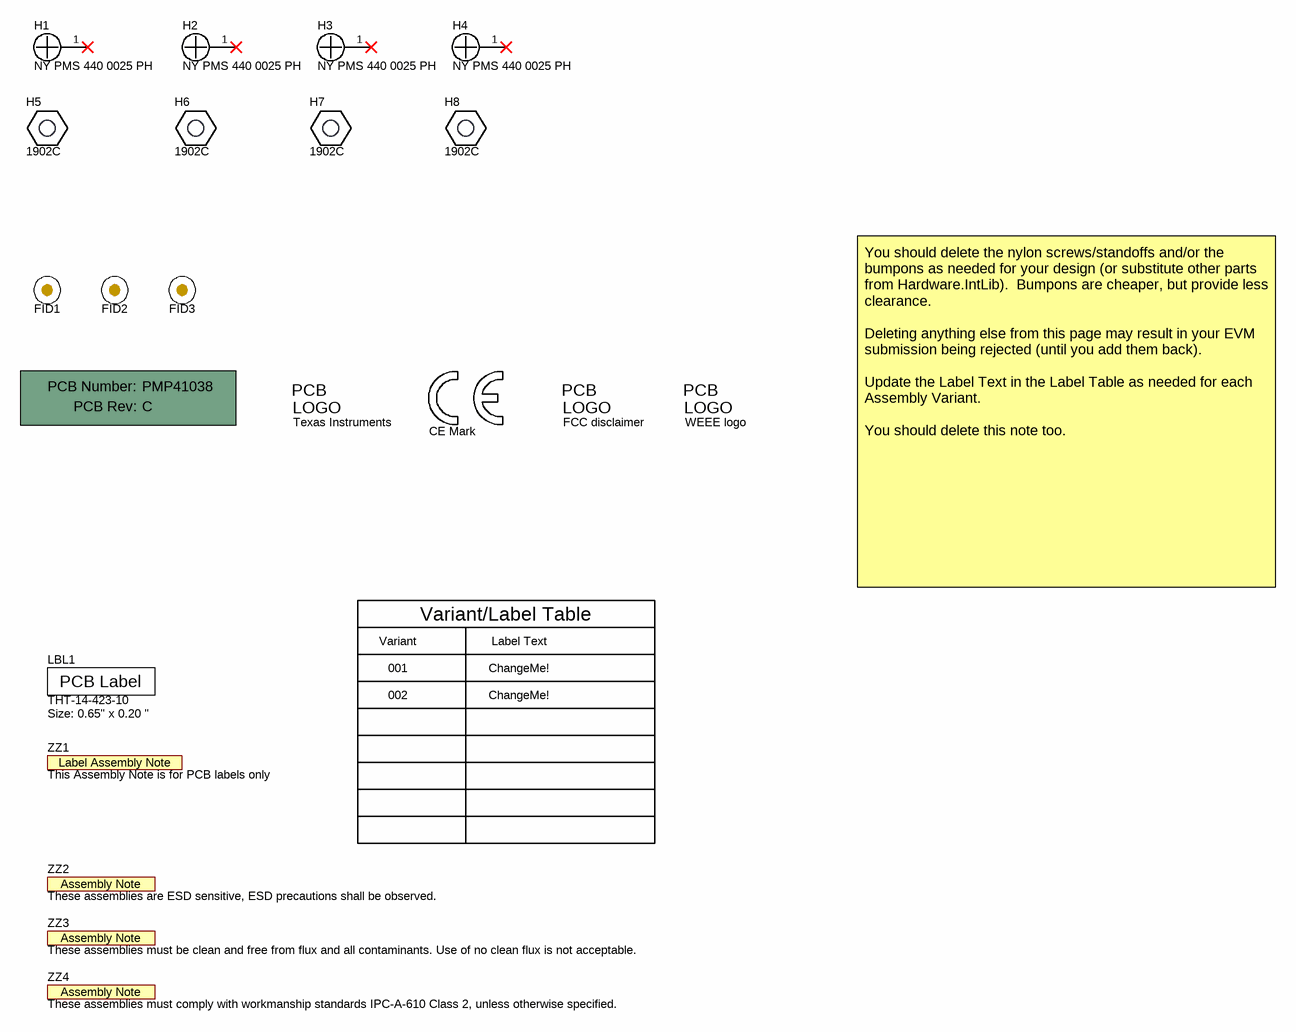
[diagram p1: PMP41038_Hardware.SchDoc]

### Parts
!PCB  Printed Circuit Board  (value not drawn)  (mechanical)
FID1  Fiducial  [Fiducial10-20]  (value not drawn)
FID2  Fiducial  [Fiducial10-20]  (value not drawn)
FID3  Fiducial  [Fiducial10-20]  (value not drawn)
H1  NY PMS 440 0025 PH  [NY PMS 440 0025 PH]
H2  NY PMS 440 0025 PH  [NY PMS 440 0025 PH]
H3  NY PMS 440 0025 PH  [NY PMS 440 0025 PH]
H4  NY PMS 440 0025 PH  [NY PMS 440 0025 PH]
H5  1902C  [Keystone_1902C]
H6  1902C  [Keystone_1902C]
H7  1902C  [Keystone_1902C]
H8  1902C  [Keystone_1902C]
LBL1  THT-14-423-10  Note: Size: 0.65" x 0.20 "  [Label_650x200]
Logo1  Texas Instruments  [TI_Stacked_Overlay_Small]  (no BOM)
Logo2  CE Mark  [CE_Mark_5mm]  (no BOM)
Logo3  FCC disclaimer  [FCC_disclaimer]  (no BOM)
Logo4  WEEE logo  [WEEE_Minimum]  (no BOM)
ZZ1  This Assembly Note is for PCB labels only  [AssemblyNoteLabel]  (no BOM)
ZZ2  These assemblies are ESD sensitive, ESD precautions shall be observed.  [AssemblyNote]  (no BOM)
ZZ3  These assemblies must be clean and free from flux and all contaminants. Use of no clean flux is not acceptable.  [AssemblyNote]  (no BOM)
ZZ4  These assemblies must comply with workmanship standards IPC-A-610 Class 2, unless otherwise specified.  [AssemblyNote]  (no BOM)

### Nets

Not connected (* = marked no-connect by the designer): H1 1*; H2 1*; H3 1*; H4 1*

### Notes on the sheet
- Variant
- Variant/Label Table
- Label Text
- You should delete the nylon screws/standoffs and/or the bumpons as needed for your design (or substitute other parts from Hardware.IntLib).  Bumpons are cheaper, but provide less clearance.
  Deleting anything else from this page may result in your EVM submission being rejected (until you add them back).
  Update the Label Text in the Label Table as needed for each Assembly Variant.
  You should delete this note too.
- 001
- 002
- ChangeMe!

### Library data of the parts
!PCB = CMP-0003618-2: Manufacturer: Any; PartNumber: PMP41038
FID1-FID3 = CMP-0077181-1: Fiducial mark.  There is nothing to buy or mount.
H1-H4 = CMP-0003617-1: Machine Screw, Round, #4-40 x 1/4, Nylon, Philips panhead; Manufacturer: B&F Fastener Supply; CompType: Hardware
H5-H8 = CMP-0003610-1: Standoff, Hex, 0.5"L #4-40 Nylon; Manufacturer: Keystone; CompType: Hardware
LBL1 = CMP-0003625-1: Thermal Transfer Printable Labels, 0.650" W x 0.200" H - 10,000 per roll; Manufacturer: Brady; CompType: Label
Logo1 = CMP-0074838-1: Texas Instrument Corporate Signature; SymbolCreator: a0412235; Lib Reference: TI_Logo; Library Reference: Logo
Logo2 = CMP-0074844-1: SymbolCreator: a0412235
Logo3 = CMP-0074847-1: FCC_disclaimer; Library Reference: Logo
Logo4 = CMP-0074769-1
ZZ1 = CMP-0003616-3
ZZ2 = CMP-0077236-1
ZZ3 = CMP-0077237-1
ZZ4 = CMP-0077238-1

## Sheet PMP41038 Driver.SchDoc
size A3; Date: Not shown in title block; ApprovedBy: Not shown in title block; CheckedBy: Not shown in title block; Author: Not shown in title block; CompanyName: Not shown in title block; Engineer: Not shown in title block; Organization: Not shown in title block; Address1: Not shown in title block; Address2: Not shown in title block; Address3: Not shown in title block; Address4: Not shown in title block; DocumentNumber: 2; Revision: Use project parameter SCH_Rev; SheetNumber: 2; SheetTotal: 3; PageSetup: Record=PageOptions¦CenterHorizontal=True¦CenterVertical=True¦PrintScale=1.00¦XCorrection=1.00¦YCorrection=1.00¦PrintKind=0¦BorderSize=5000000¦LeftOffset=0¦BottomOffset=0¦Orientation=2¦PaperLength=1000¦PaperWidth=1000¦Scale=100¦PaperSource=15¦PrintQuality=600¦MediaType=1¦DitherType=10¦PaperKind=Letter¦PrintScaleMode=1
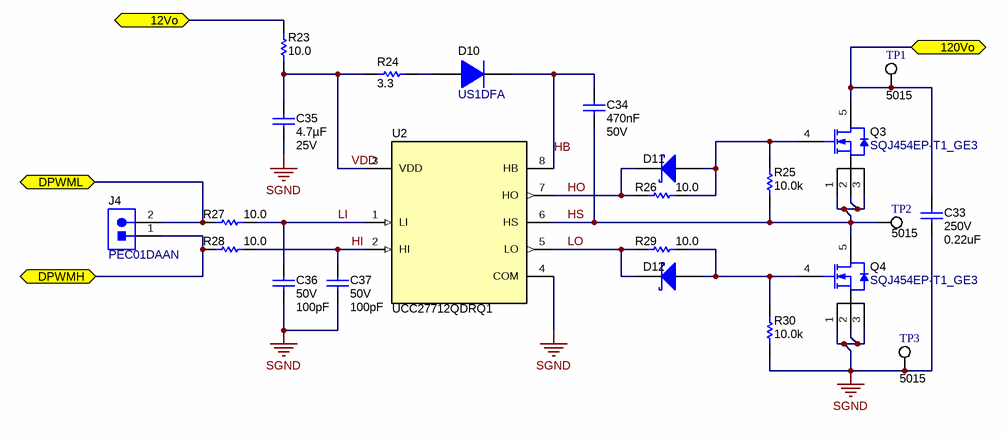
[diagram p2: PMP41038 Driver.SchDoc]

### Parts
C33  VDC_V: 250V  ValueDisplayed: 0.22uF  [1210_220]  (hidden comment: GRM32DR72E224KW01L)
C34  Cap_F: 470nF  VDC_V: 50V  [0805_HV]  (hidden comment: GCM21BR71H474KA55L)
C35  Cap_F: 4.7µF  VDC_V: 25V  [0805L]  (hidden comment: CGA4J1X7R1E475K125AC)
C36  VDC_V: 50V  ValueDisplayed: 100pF  [0402]  (hidden comment: CGA2B2C0G1H101J050BA)
C37  VDC_V: 50V  ValueDisplayed: 100pF  [0402]  (hidden comment: CGA2B2C0G1H101J050BA)
D10  US1DFA  [SOD-123FA]
D11  BAT54WSQ-7-F  [SOD-323]  (value not drawn)
D12  BAT54WSQ-7-F  [SOD-323]  (value not drawn)
J4  PEC01DAAN  [Sullins_PxC01DAAN]
Q3  SQJ454EP-T1_GE3  [PowerPAK_SO-8L]
Q4  SQJ454EP-T1_GE3  [PowerPAK_SO-8L]
R23  ValueDisplayed: 10.0  [0603]  (hidden comment: CRCW060310R0FKEAHP)
R24  ValueDisplayed: 3.3  [0603]  (hidden comment: CRCW06033R30JNEA)
R25  ValueDisplayed: 10.0k  [0402]  (hidden comment: RMCF0402FT10K0)
R26  ValueDisplayed: 10.0  [0603]  (hidden comment: CRCW060310R0FKEAHP)
R27  ValueDisplayed: 10.0  [0402]  (hidden comment: CRCW040210R0FKED)
R28  ValueDisplayed: 10.0  [0402]  (hidden comment: CRCW040210R0FKED)
R29  ValueDisplayed: 10.0  [0603]  (hidden comment: CRCW060310R0FKEAHP)
R30  ValueDisplayed: 10.0k  [0402]  (hidden comment: RMCF0402FT10K0)
TP1  5015  [Testpoint_Keystone_Miniature]
TP2  5015  [Testpoint_Keystone_Miniature]
TP3  5015  [Testpoint_Keystone_Miniature]
U2  UCC27712QDRQ1  [D0008A_N]

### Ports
12Vo (bidir), 120Vo (bidir), DPWMH (bidir), DPWML (bidir)

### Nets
SGND: C33.2 C35.2 C36.2 C37.2 Q4.1(S) Q4.2(S) Q4.3(S) R30.1 TP3.1 U2.4(COM)
12Vo: R23.2 ; port 12Vo
120Vo: C33.1 Q3.5(D) TP1.1 ; port 120Vo
DPWMH: J4.1 R28.1 ; port DPWMH
DPWML: J4.2 R27.1 ; port DPWML
HB: C34.1 D10.1(K) U2.8(HB)
HI: C37.1 R28.2 U2.2(HI)
HO: D11.1(K) R26.1 U2.7(HO)
HS: C34.2 Q3.1(S) Q3.2(S) Q3.3(S) Q4.5(D) R25.1 TP2.1 U2.6(HS)
LI: C36.1 R27.2 U2.1(LI)
LO: D12.1(K) R29.1 U2.5(LO)
VDD: C35.1 R23.1 R24.1 U2.3(VDD)
NetD10_2: D10.2(A) R24.2
NetD11_2: D11.2(A) Q3.4(G) R25.2 R26.2
NetD12_2: D12.2(A) Q4.4(G) R29.2 R30.2

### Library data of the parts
C33 = CMP-0009193-2: as C12 on sheet PMP41038 PowerSupply
C34 = CMP-0008022-1: CAP, CERM, 0.47 uF, 50 V, +/- 10%, X7R, AEC-Q200 Grade 1, 0805; Manufacturer: MuRata; TaMin_C: -55°C; Polarized: N; SizeAreaWB_mm2: 6.75; Value1: Unknown; U/M: EA; Value: 0.47uF; TaMax_C: 125°C; SizeZ_mm: 1.45; SizeX_mm: 2; SizeY_mm: 1.25; Cap_Case: 0805; SizeArea_mm2: 2.5; AEC Qualified: Y; AEC Grade: 1; AEC Category: Q200
C35 = CMP-0076706-1: CAP, CERM, 4.7 µF, 25 V,+/- 10%, X7R, AEC-Q200 Grade 1, 0805; Manufacturer: TDK; SizeAreaWB_mm2: 6.75; SizeArea_mm2: 2.5; AEC Qualified: Y; AEC Category: Q200; Value: 4.7uF; TaMax_C: 125°C; SizeZ_mm: 1.45; AEC Grade: 1; Polarized: N; TaMin_C: -55°C; SizeY_mm: 1.25; U/M: EA; SizeX_mm: 2.0; Cap_Case: 2x1.25x1.25mm
C36 C37 = CMP-0006308-1: CAP, CERM, 100 pF, 50 V, +/- 5%, C0G/NP0, AEC-Q200 Grade 1, 0402; Manufacturer: TDK; TaMin_C: -55°C; Polarized: N; SizeAreaWB_mm2: 3; Value1: Unknown; U/M: EA; Value: 100pF; TaMax_C: 125°C; SizeZ_mm: 0.6; SizeX_mm: 1; SizeY_mm: 0.5; AEC Qualified: Y; AEC Category: Q200
D10 = CMP-0084320-2: Diode, Superfast Rectifier, 200 V, 1 A, AEC-Q101, 2.8x1.8mm; Manufacturer: Fairchild Semiconductor; Value2: 0.95V; SizeAreaWB_mm2: 12.88; Vr_V: 200V; TJmax_C: 150°C; Io_A: 1A; SizeZ_mm: 1.43; SizeY_mm: 1.8; AEC Category: Q101; Value: 200V; SizeX_mm: 3.6; SizeArea_mm2: 6.48; Vf_V: 950mV; AEC Qualified: Y
D11 D12 = CMP-0081199-2: as D9 on sheet PMP41038 PowerSupply
J4 = CMP-0054594-1: Header, 2.54mm, 1x2, Tin, Black, TH; Manufacturer: Sullins Connector Solutions; CNHeader: TRUE; Current_A: 3A; Green_Lifecycle: Active; Shrouded: N; Gender: Male; Green_REACh: Passed; Voltage_V: 1.8kV; Row_Count: 2; RowSpacing_mm: 2.54; CT: FALSE; Cert_UL: Y
Q3 Q4 = CMP-0085316-1: MOSFET, N-CH, 200 V, 13 A, AEC-Q101, PowerPAK_SO-8L; Alternate Manufacturer: None; Manufacturer: Vishay-Siliconix; VdsMax_V: 200V; Value2: 56 nC; SizeZ_mm: 1.14; QgTyp_nC: 56; Value: 200V; ChMode: Enhancement; AEC Qualified: Y; SizeX_mm: 6.15; IdsMax_A: 13A; Vgs_V: 20V; AEC Category: Q101; Value1: 0.15 ohm; SizeY_mm: 5.13; ChType: N; SizeArea_mm2: 31.5495; SizeAreaWB_mm2: 58.1095; Rdson45_ohm: 0.15
R23 R26 R29 = CMP-0022004-4: RES, 10.0, 1%, 0.25 W, AEC-Q200 Grade 0, 0603; Manufacturer: Vishay-Dale; Power_W: 250mW; TempCo: 100 ppm/C; Value_Code: 10R0; Value: 10.0; EIA_Code: E96; Res_ohm: 10; SizeX_mm: 1.6; SizeY_mm: 0.8; SizeZ_mm: 1; Value2: 0.25W; SizeArea_mm2: 1.28; AEC Qualified: Y; VDC_V: 75V; AEC Category: Q200; AEC Grade: 0
R24 = CMP-0025805-4: RES, 3.3, 5%, 0.1 W, AEC-Q200 Grade 0, 0603; Manufacturer: Vishay-Dale; Power_W: 100mW; TempCo: 200 ppm/C; Value_Code: 3R30; Value: 3.3; EIA_Code: E24; SizeX_mm: 1.6; SizeY_mm: 0.8; SizeZ_mm: 1; Value2: 0.1W; SizeArea_mm2: 1.28; AEC Qualified: Y; VDC_V: 75V; AEC Category: Q200; AEC Grade: 0
R25 R30 = CMP-0026754-1: RES, 10.0 k, 1%, 0.063 W, AEC-Q200 Grade 0, 0402; Manufacturer: Stackpole Electronics Inc; Power_W: 63mW; TempCo: 100 ppm/C; Value_Code: 10k0; U/M: EA; Value: 10.0k; EIA_Code: E96; Res_ohm: 10k; SizeX_mm: 1; SizeY_mm: 0.5; SizeZ_mm: 0.6; Value2: 0.063W; AEC Qualified: Y; VDC_V: 50V; AEC Grade: 0; AEC Category: Q200
R27 R28 = CMP-0025963-3: RES, 10.0, 1%, 0.063 W, AEC-Q200 Grade 0, 0402; Manufacturer: Vishay-Dale; Power_W: 63mW; TempCo: 100 ppm/C; Value_Code: 10R0; Value: 10.0; EIA_Code: E96; Res_ohm: 10; SizeX_mm: 1; SizeY_mm: 0.5; SizeZ_mm: 0.6; Value2: 0.063W; AEC Qualified: Y; VDC_V: 50V; AEC Category: Q200; AEC Grade: 0
TP1-TP3 = CMP-0055152-1: Test Point, Miniature, SMT; Manufacturer: Keystone; CNHeader: FALSE; Green_Lifecycle: Active; Green_REACh: Passed; CT: TRUE
U2 = CMP-0065057-2: 620-V High-Side Low-Side Gate Driver with 2.5A Peak Output and RobustDrive, D0008A (SOIC-8); Manufacturer: Texas Instruments; SizeX_mm: 4.9; SizeY_mm: 6.2; CompType: IC; SizeZ_mm: 1.75; SizeArea_mm2: 30.38; SizeAreaWB_mm2: 56.58; U/M: EA

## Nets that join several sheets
SGND: PMP41038 PowerSupply (19 pins), PMP41038 Driver (10 pins)
12Vo: PMP41038 PowerSupply (9 pins), PMP41038 Driver (R23.2)
120Vo: PMP41038 PowerSupply (11 pins), PMP41038 Driver (C33.1 Q3.5 TP1.1)

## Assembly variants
001: not fitted FID1 FID2 FID3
